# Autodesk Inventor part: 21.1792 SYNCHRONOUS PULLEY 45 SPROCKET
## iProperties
Created: 2007-05
Part Number: 21.1792 SYNCHRONOUS PULLEY 45 SPROCKET
Document SubType Name: Modeling
Designer: Andy Moles
Material: Steel
Density: 7.85 g/cm^3
Author: Andy Moles
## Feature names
1. Base1
2. Hole1
3. Hole2
